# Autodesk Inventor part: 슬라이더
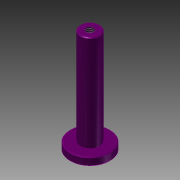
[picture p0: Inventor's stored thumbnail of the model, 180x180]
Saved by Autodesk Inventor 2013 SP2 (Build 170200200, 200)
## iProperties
Created: 2016-02
Part Number: 슬라이더
Material: 스테인리스강
Document SubType Name: Modeling
Designer: mduedu
Density: 8.08 g/cm^3
Author: mduedu
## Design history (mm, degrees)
sketch "스케치1"
  geometry: C1 r 12.5 at (0, 0); 1 further point
  constraints: 1 centre point, 1 coincident
  dimensions: "d0" = 25 diameter of C1
extrude "돌출1" new body sketch "스케치1" distance "d1" = 5; taper "d2" = 0 deg
sketch "스케치2"
  geometry: C1 r 6 at (0, 0); 1 further point
  constraints: 1 centre point, 1 coincident
  dimensions: "d3" = 12 diameter of C1
extrude "돌출2" join sketch "스케치2" distance "d4" = 60; taper "d5" = 0 deg
chamfer "모따기1" distance "d6" = 0.5; stored, may be unused: second distance "d7" = 2, angle "d8" = 45 deg
hole "구멍1" diameter "d11" = 4.917; stored, may be unused: countersink angle "d15" = 90 deg, drill point angle "d17" = 118 deg; dims "d9" = 10, "d10" = 10, "d12" = 10, "d13" = 4, "d14" = 2, "d16" = 12
chamfer "모따기2" distance "d18" = 0.5; stored, may be unused: second distance "d19" = 2, angle "d20" = 45 deg
node "솔리드1"
